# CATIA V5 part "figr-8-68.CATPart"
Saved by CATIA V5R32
Part number: Part1
Bounding box of the stored display mesh (mm): x -84.762 to 84.762, y -75 to 75, z 0 to 50
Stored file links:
  D:\PROJECTS\Project 2022\CATIA V5 6R 2022\Resources\Part Files\c08_catia_v5_6r2022_prt\figr-8-68.CATPart
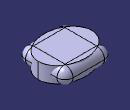
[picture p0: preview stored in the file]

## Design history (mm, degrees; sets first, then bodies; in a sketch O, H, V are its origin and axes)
Body1 (main body)
  Sketch1 on xy-plane, origin (0, 0, 0), H (1, 0, 0), V (0, 1, 0)
    line L1 (-75, 75) -> (75, 75)
    line L2 (75, 75) -> (75, -75)
    line L3 (75, -75) -> (-75, -75)
    line L4 (-75, -75) -> (-75, 75)
    axis line L5 (75, -75) -> (-75, 75)
    length L3 = 150
    length L2 = 150
    horizontal: L1 H, L3 H
    vertical: L2 V, L4 V
    midpoint: O L5
  Pad1: profile Sketch1, direction (0, 0, 1), length 50
  Fillet1: radius 25, on face of Pad1 (x6)
Body2
  Sketch2 on xy-plane, origin (0, 0, 0), H (1, 0, 0), V (0, 1, 0)
    ellipse A1 centre (0, 0) semi-axes 84.7617, 65.8627 rotation 0
    point P1 (84.7617, 0)
    point P2 (0, 65.8627)
    coincidence: P1 H, P2 V, A1 P1, A1 P2
  Pad2: profile Sketch2, direction (0, 0, 1), length 50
